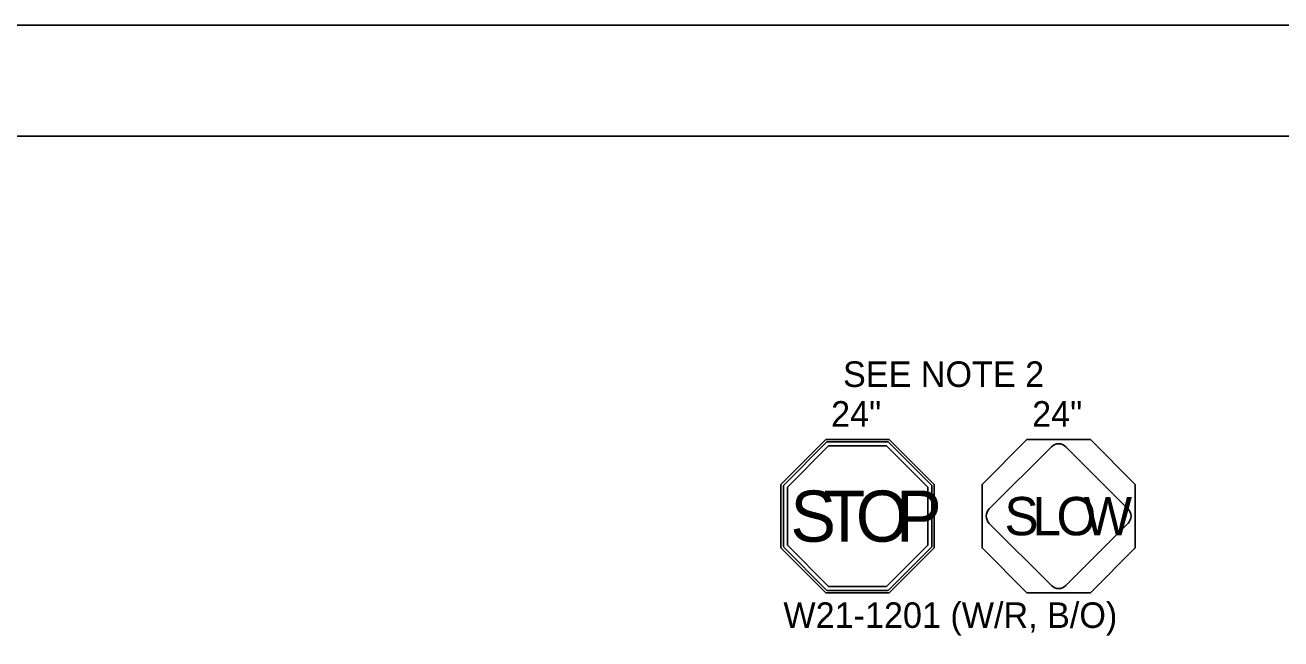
# Model space of a CAD drawing. Extents: x 99999.1 to 100095.7, y 99995 to 100010.7.
# Drawn here: x 100048.842 to 100052.384, y 100008.958 to 100010.687 of the extents above; entities that cross this region are included whole.
import ezdxf

# ---------------------------------------------------------------- set-up
doc = ezdxf.new("R2010")
doc.units = 0
for name, color, linetype in [('SH_GI_PlotLimits', 7, 'Continuous'), ('SH_GI_SheetBorder', 7, 'Continuous'), ('TR_SN_ConstructionSigns', 7, 'Continuous')]:
    doc.layers.add(name, color=color, linetype=linetype)

msp = doc.modelspace()

# ---------------------------------------------------------------- linework, layer by layer
at = {"layer": 'SH_GI_PlotLimits'}
msp.add_lwpolyline([(100039.0625, 99999.6875), (100056.0625, 99999.6875), (100056.0625, 100010.6875), (100039.0625, 100010.6875)], close=True, dxfattribs=at)
at = {"layer": 'SH_GI_SheetBorder'}
msp.add_line((100040, 100010.375), (100055.75, 100010.375), dxfattribs=at)
at = {"layer": 'TR_SN_ConstructionSigns'}
for p, q in [((100051.1006, 100009.5201), (100050.9741, 100009.3936)), ((100051.1034, 100009.5134), (100050.9809, 100009.3908)), ((100050.9921, 100009.3861), (100051.1081, 100009.5021)), ((100051.2796, 100009.5201), (100051.1006, 100009.5201)), ((100051.2768, 100009.5134), (100051.1034, 100009.5134)), ((100051.1081, 100009.5021), (100051.2721, 100009.5021)), ((100051.2721, 100009.5021), (100051.3881, 100009.3861)), ((100051.3994, 100009.3908), (100051.2768, 100009.5134)), ((100051.4061, 100009.3936), (100051.2796, 100009.5201)), ((100051.7367, 100009.4997), (100051.5615, 100009.3245)), ((100051.9527, 100009.3245), (100051.7775, 100009.4997)), ((100050.9741, 100009.3936), (100050.9741, 100009.2146)), ((100050.9809, 100009.3908), (100050.9809, 100009.2174)), ((100050.9921, 100009.2221), (100050.9921, 100009.3861)), ((100051.3881, 100009.3861), (100051.3881, 100009.2221)), ((100051.3994, 100009.2174), (100051.3994, 100009.3908)), ((100051.4061, 100009.2146), (100051.4061, 100009.3936)), ((100051.5615, 100009.2837), (100051.7367, 100009.1085)), ((100051.7775, 100009.1085), (100051.9527, 100009.2837)), ((100050.9741, 100009.2146), (100051.1006, 100009.0881)), ((100050.9809, 100009.2174), (100051.1034, 100009.0949)), ((100051.1081, 100009.1061), (100050.9921, 100009.2221)), ((100051.3881, 100009.2221), (100051.2721, 100009.1061)), ((100051.2768, 100009.0949), (100051.3994, 100009.2174)), ((100051.2796, 100009.0881), (100051.4061, 100009.2146)), ((100051.2721, 100009.1061), (100051.1081, 100009.1061)), ((100051.1006, 100009.0881), (100051.2796, 100009.0881)), ((100051.1034, 100009.0949), (100051.2768, 100009.0949))]:
    msp.add_line(p, q, dxfattribs=at)
msp.add_lwpolyline([(100051.9731, 100009.3936), (100051.9731, 100009.2146), (100051.8466, 100009.0881), (100051.6676, 100009.0881), (100051.5411, 100009.2146), (100051.5411, 100009.3936), (100051.6676, 100009.5201), (100051.8466, 100009.5201)], close=True, dxfattribs=at)
for centre, start, end in [((100051.7571, 100009.4794), 45, 135), ((100051.5818, 100009.3041), 135, 225), ((100051.9324, 100009.3041), 315, 45), ((100051.7571, 100009.1288), 225, 315)]:
    msp.add_arc(centre, 0.0288, start, end, dxfattribs=at)

# ---------------------------------------------------------------- texts
for s, p in [('SEE NOTE 2', (100051.149, 100009.6681)), ('W21-1201 (W/R, B/O)', (100050.9809, 100008.9891))]:
    msp.add_text(s, height=0.072, rotation=360, dxfattribs=at).set_placement(p)
for s, height, p in [('24"', 0.072, (100051.1154, 100009.5561)), ('24"', 0.072, (100051.6824, 100009.5561)), ('S', 0.144, (100051.0007, 100009.2321)), ('T', 0.144, (100051.0943, 100009.2321)), ('O', 0.144, (100051.1851, 100009.2321)), ('P', 0.144, (100051.2988, 100009.2321)), ('S', 0.108, (100051.6043, 100009.2501)), ('L', 0.108, (100051.6831, 100009.2501)), ('O', 0.108, (100051.7512, 100009.2501)), ('W', 0.108, (100051.8279, 100009.2501))]:
    msp.add_text(s, height=height, dxfattribs=at).set_placement(p)

doc.saveas('drawing.dxf')
